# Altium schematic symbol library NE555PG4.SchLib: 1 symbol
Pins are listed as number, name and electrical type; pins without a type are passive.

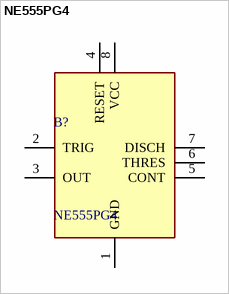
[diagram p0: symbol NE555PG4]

## NE555PG4
designator B?
Precision timer, PDIP-8; Manufacturer_Name: Texas Instruments; Geometry.Height: 5.08mm
footprint DIP794W53P254L959H508Q8N
pins: 1 GND, 2 TRIG, 3 OUT, 4 RESET, 5 CONT, 6 THRES, 7 DISCH, 8 VCC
